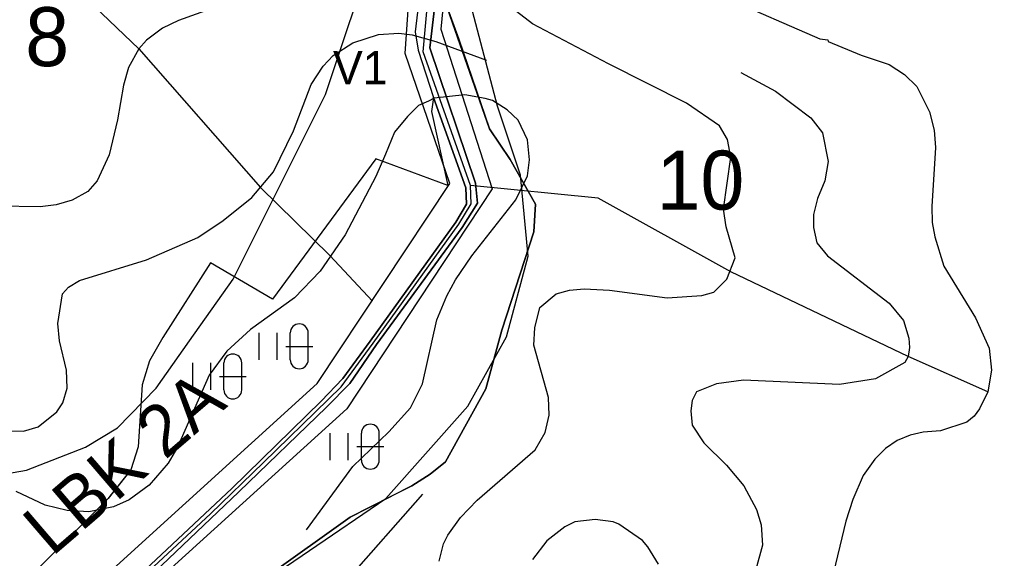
# Model space of a CAD drawing. Extents: x -662500 to -655523, y -1056000 to -1049993.
# Drawn here: x -660066.2 to -659685.9, y -1052866.9 to -1052656.8 of the extents above; entities that cross this region are included whole.
import ezdxf

# ---------------------------------------------------------------- set-up
doc = ezdxf.new("R2010")
doc.units = 0
for name, color, linetype in [('Vrstva 24', 7, 'Continuous'), ('Vrstva 32', 7, 'Continuous'), ('Vrstva 5', 7, 'Continuous'), ('Vrstva 51', 7, 'Continuous'), ('Vrstva 57', 7, 'Continuous'), ('Vrstva 7', 7, 'Continuous'), ('Vrstva 9', 7, 'Continuous')]:
    doc.layers.add(name, color=color, linetype=linetype)

msp = doc.modelspace()

# ---------------------------------------------------------------- linework, layer by layer
at = {"layer": 'Vrstva 24'}
for points in [[(-660034, -1052954), (-660032, -1052948.5), (-660000, -1052906.38), (-659983, -1052884), (-659923.5, -1052843.5), (-659891.5, -1052807.5), (-659876.5, -1052780.5), (-659868, -1052749), (-659871, -1052717.5), (-659880, -1052690.5), (-659893, -1052641), (-659893, -1052609.5), (-659864.5, -1052533), (-659861.5, -1052506), (-659866.5, -1052474.5), (-659880.5, -1052438.5), (-659901.5, -1052398), (-659927, -1052348.5), (-659940, -1052302)], [(-660132, -1052865), (-660131.5, -1052853), (-660124, -1052843), (-660063.5, -1052832.5), (-660040.5, -1052823.5), (-660028, -1052816), (-660013, -1052800.5), (-660000, -1052782.08), (-659983, -1052758), (-659947, -1052686), (-659927.5, -1052627.5), (-659920, -1052581), (-659923.5, -1052545), (-659933, -1052515), (-659946, -1052493), (-659958.5, -1052479), (-659977, -1052460), (-660000, -1052444.36), (-660002, -1052443), (-660058, -1052408.5), (-660084, -1052396), (-660097, -1052392.5), (-660103, -1052390), (-660138, -1052390)]]:
    msp.add_lwpolyline(points, dxfattribs=at)
at = {"layer": 'Vrstva 32'}
msp.add_lwpolyline([(-660043.52, -1052897.56), (-659991.83, -1052849.55), (-659971.21, -1052829.43), (-659940.88, -1052799.92), (-659928.36, -1052782.89), (-659895.08, -1052736.55), (-659890.22, -1052728.7), (-659890.47, -1052721.49), (-659908.9, -1052669.32), (-659905.49, -1052630.68), (-659904.41, -1052599.95), (-659898.52, -1052575.7), (-659893.12, -1052552.53), (-659895.67, -1052538.64), (-659900.78, -1052506.64), (-659903.72, -1052495.05), (-659933.15, -1052395.84), (-659942.2, -1052359.57), (-659946.03, -1052344.26)], dxfattribs=at)
at = {"layer": 'Vrstva 5'}
for points in [[(-659488.42, -1052589.49), (-659931.7, -1052394.49), (-659912.55, -1052459.34), (-659898.17, -1052506.06), (-659891.78, -1052526.8), (-659889.85, -1052537.24), (-659889.84, -1052553.2), (-659891.97, -1052560.5), (-659899.91, -1052591.56), (-659902.26, -1052610.6), (-659903.49, -1052643.35), (-659900.3, -1052649.88), (-659895.05, -1052664.49), (-659883.07, -1052699.38), (-659874.97, -1052711.4), (-659865.21, -1052728.83), (-659865.78, -1052739.54), (-659878.28, -1052777.87), (-659884.49, -1052800.77), (-659900.19, -1052829.18), (-659906.2, -1052834), (-659913.38, -1052838.57), (-659937.32, -1052850.73), (-659969.58, -1052873.81)], [(-659909.98, -1052643.89), (-659912.09, -1052661.63), (-659910.92, -1052668.79), (-659904.94, -1052687.24), (-659905.71, -1052692.7), (-659899.37, -1052721.44), (-659927.4, -1052711.06), (-659967.63, -1052765.86), (-659991.81, -1052751.6), (-660010.37, -1052780.75), (-660015.6, -1052789.79), (-660018.46, -1052799.22), (-660019.99, -1052823.38), (-660022.81, -1052832.29), (-660031.73, -1052843.45), (-660064, -1052875.84)], [(-659909.98, -1052643.89), (-659912.09, -1052661.63), (-659910.92, -1052668.79), (-659904.94, -1052687.24), (-659892.37, -1052722.42), (-659892.1, -1052728.71), (-659896.18, -1052735.72), (-659929.58, -1052782.17), (-659940.23, -1052796.79), (-659948.71, -1052805.54), (-659983.56, -1052839.55), (-660021.37, -1052875.26)], [(-659969.58, -1052873.81), (-659937.32, -1052850.73), (-659918.06, -1052840.85), (-659913.38, -1052838.57), (-659906.2, -1052834), (-659900.19, -1052829.18), (-659884.49, -1052800.77), (-659878.28, -1052777.87), (-659865.78, -1052739.54), (-659865.21, -1052728.83), (-659874.97, -1052711.4), (-659883.07, -1052699.38), (-659900.3, -1052649.88), (-659903.49, -1052643.35), (-659906.35, -1052667.8), (-659888.54, -1052720.54), (-659887.79, -1052728.34), (-659893.7, -1052737.91), (-659927.06, -1052783.51), (-659937.57, -1052798.73), (-659946.56, -1052807.92), (-659980.71, -1052840.86), (-660019.16, -1052877.46)], [(-660019.16, -1052877.46), (-659980.71, -1052840.86), (-659946.56, -1052807.92), (-659937.57, -1052798.73), (-659927.06, -1052783.51), (-659893.7, -1052737.91), (-659887.79, -1052728.34), (-659888.54, -1052720.54), (-659906.35, -1052667.8), (-659903.49, -1052643.35)], [(-660021.37, -1052875.26), (-659983.56, -1052839.55), (-659948.71, -1052805.54), (-659940.23, -1052796.79), (-659929.58, -1052782.17), (-659896.18, -1052735.72), (-659892.1, -1052728.71), (-659892.37, -1052722.42), (-659904.94, -1052687.24), (-659905.71, -1052692.7), (-659899.37, -1052721.44), (-659927.4, -1052711.06), (-659967.63, -1052765.86), (-659991.81, -1052751.6), (-660010.37, -1052780.75), (-660015.6, -1052789.79), (-660018.46, -1052799.22), (-660019.99, -1052823.38), (-660022.81, -1052832.29), (-660031.02, -1052842.56), (-660031.73, -1052843.45), (-660064, -1052875.84)], [(-659972.99, -1052778.94), (-659972.99, -1052789.44)], [(-659965.99, -1052778.94), (-659965.99, -1052789.44)], [(-659960.74, -1052789.44), (-659960.74, -1052778.94)], [(-659953.74, -1052789.44), (-659953.74, -1052778.94)], [(-659962.49, -1052784.19), (-659951.99, -1052784.19)]]:
    msp.add_lwpolyline(points, dxfattribs=at)
for centre, start, end in [((-659957.24, -1052778.94), 0, 180), ((-659957.24, -1052789.44), 180, 0)]:
    msp.add_arc(centre, 3.5, start, end, dxfattribs=at)
at = {"layer": 'Vrstva 51'}
for points in [[(-660169.13, -1053023.13), (-660110.85, -1052940.58), (-660079.74, -1052916.29), (-659950.2, -1052798.66), (-659898.58, -1052720.65), (-659915.89, -1052669.98), (-659910.89, -1052596.38), (-659900.42, -1052552.71), (-659942.19, -1052387.83), (-659921.6, -1052399.48), (-659893.5, -1052409.43), (-659785.78, -1052462.16), (-659600.37, -1052554.27), (-659621.1, -1052589.25), (-659403.17, -1052709.23)], [(-659408.68, -1052722.85), (-659645.22, -1052595.6), (-659623.64, -1052558.85), (-659899.32, -1052423.28), (-659921, -1052417.16), (-659884.97, -1052552.61), (-659896.01, -1052598.65), (-659902.05, -1052660.61), (-659882, -1052722.78), (-659938.73, -1052808.5), (-660070.07, -1052927.77), (-660099.87, -1052951.04), (-660151.35, -1053023.96)]]:
    msp.add_lwpolyline(points, dxfattribs=at)
at = {"layer": 'Vrstva 57'}
for points in [[(-660144.85, -1052500.62), (-660117.36, -1052556.07), (-660071.54, -1052618.58), (-660019.78, -1052668.15), (-659972.38, -1052722.21), (-659945.35, -1052748.76), (-659928.67, -1052766.62)], [(-659688.88, -1052801.93), (-659719.91, -1052788.18), (-659789.09, -1052755.11), (-659840.79, -1052726.44), (-659890.47, -1052721.49)]]:
    msp.add_lwpolyline(points, dxfattribs=at)
at = {"layer": 'Vrstva 7'}
for p, q in [((-659803.38, -1052642.92), (-659754.35, -1052664.32)), ((-659988.75, -1052651.56), (-660004.34, -1052657.23)), ((-659866.38, -1052658.42), (-659877.61, -1052649.73)), ((-660004.34, -1052657.23), (-660010.57, -1052660.21)), ((-660010.57, -1052660.21), (-660016.81, -1052664.89)), ((-659836.69, -1052674.1), (-659866.38, -1052658.42)), ((-659936.31, -1052665.88), (-659926.39, -1052662.62)), ((-659926.39, -1052662.62), (-659918.46, -1052662.05)), ((-659918.46, -1052662.05), (-659913.21, -1052662.76)), ((-659913.21, -1052662.76), (-659904, -1052665.31)), ((-659754.35, -1052664.32), (-659751.23, -1052664.75)), ((-659751.23, -1052664.75), (-659751.09, -1052665.31)), ((-660019.78, -1052668.15), (-660023.75, -1052675.52)), ((-660016.81, -1052664.89), (-660019.78, -1052668.15)), ((-659943.97, -1052670.84), (-659936.31, -1052665.88)), ((-659904, -1052665.31), (-659884.3, -1052672.68)), ((-659751.09, -1052665.31), (-659738.19, -1052670.7)), ((-659947.93, -1052674.95), (-659943.97, -1052670.84)), ((-659738.19, -1052670.7), (-659727.28, -1052674.38)), ((-660023.75, -1052675.52), (-660025.74, -1052682.32)), ((-659952.61, -1052682.18), (-659947.93, -1052674.95)), ((-659806.36, -1052689.4), (-659836.69, -1052674.1)), ((-659727.28, -1052674.38), (-659721.33, -1052678.21)), ((-659785.1, -1052677.5), (-659771.64, -1052684.73)), ((-659721.33, -1052678.21), (-659716.51, -1052682.89)), ((-660025.74, -1052682.32), (-660028, -1052695.92)), ((-659959.41, -1052700.17), (-659952.61, -1052682.18)), ((-659716.51, -1052682.89), (-659711.55, -1052692.8)), ((-659904.65, -1052687.39), (-659906.9, -1052688.56)), ((-659892.71, -1052686.16), (-659904.65, -1052687.39)), ((-659884.73, -1052687.56), (-659892.71, -1052686.16)), ((-659881.9, -1052688.41), (-659884.73, -1052687.56)), ((-659771.64, -1052684.73), (-659757.89, -1052695.07)), ((-659910.74, -1052690.26), (-659915.05, -1052694.56)), ((-659906.9, -1052688.56), (-659910.74, -1052690.26)), ((-659876.23, -1052691.95), (-659881.9, -1052688.41)), ((-659793.46, -1052698.19), (-659806.36, -1052689.4)), ((-659915.05, -1052694.56), (-659920.07, -1052700.67)), ((-659871.97, -1052696.06), (-659876.23, -1052691.95)), ((-659757.89, -1052695.07), (-659753.36, -1052701.02)), ((-659711.55, -1052692.8), (-659709.85, -1052699.89)), ((-660028, -1052695.92), (-660031.26, -1052709.53)), ((-659868.29, -1052703.72), (-659871.97, -1052696.06)), ((-659790.35, -1052703.57), (-659793.46, -1052698.19)), ((-659967.21, -1052716.19), (-659959.41, -1052700.17)), ((-659920.07, -1052700.67), (-659923.56, -1052709.24)), ((-659753.36, -1052701.02), (-659751.09, -1052712.08)), ((-659709.85, -1052699.89), (-659709.28, -1052706.69)), ((-659867.44, -1052711.51), (-659868.29, -1052703.72)), ((-659789.07, -1052710.38), (-659790.35, -1052703.57)), ((-659709.28, -1052706.69), (-659710.7, -1052729.65)), ((-660031.26, -1052709.53), (-660035.94, -1052719.73)), ((-659923.56, -1052709.24), (-659927.39, -1052718.03)), ((-659791.91, -1052730.78), (-659789.07, -1052710.38)), ((-659868.29, -1052717.75), (-659867.44, -1052711.51)), ((-659751.09, -1052712.08), (-659752.36, -1052719.73)), ((-659975.71, -1052726.11), (-659967.21, -1052716.19)), ((-659927.39, -1052718.03), (-659939.29, -1052740.71)), ((-659872.83, -1052727.1), (-659868.29, -1052717.75)), ((-660035.94, -1052719.73), (-660039.62, -1052723.84)), ((-659752.36, -1052719.73), (-659755.2, -1052726.53)), ((-660039.62, -1052723.84), (-660045.72, -1052727.24)), ((-660058.19, -1052729.79), (-660083.13, -1052729.51)), ((-660051.95, -1052729.08), (-660058.19, -1052729.79)), ((-660045.72, -1052727.24), (-660051.95, -1052729.08)), ((-659986.91, -1052735.18), (-659975.71, -1052726.11)), ((-659889.97, -1052748.93), (-659872.83, -1052727.1)), ((-659755.2, -1052726.53), (-659756.76, -1052732.77)), ((-659790.91, -1052737.59), (-659791.91, -1052730.78)), ((-659756.76, -1052732.77), (-659756.76, -1052737.87)), ((-659710.7, -1052729.65), (-659710.56, -1052735.89)), ((-659996.69, -1052741.7), (-659986.91, -1052735.18)), ((-659710.56, -1052735.89), (-659709.57, -1052741.55)), ((-659939.29, -1052740.71), (-659949.07, -1052754.88)), ((-659787.37, -1052749.63), (-659790.91, -1052737.59)), ((-659756.76, -1052737.87), (-659755.48, -1052743.82)), ((-660016.81, -1052750.48), (-659996.69, -1052741.7)), ((-659755.48, -1052743.82), (-659751.37, -1052748.92)), ((-659709.57, -1052741.55), (-659706.02, -1052752.89)), ((-660042.89, -1052758.56), (-660016.81, -1052750.48)), ((-659896.35, -1052758.28), (-659889.97, -1052748.93)), ((-659790.63, -1052758), (-659787.37, -1052749.63)), ((-659751.37, -1052748.92), (-659727.28, -1052767.35)), ((-659949.07, -1052754.88), (-659959.13, -1052765.22)), ((-659706.02, -1052752.89), (-659693.7, -1052773.02)), ((-660047.14, -1052761.11), (-660042.89, -1052758.56)), ((-659899.75, -1052764.51), (-659896.35, -1052758.28)), ((-659795.59, -1052763.1), (-659790.63, -1052758)), ((-660051.25, -1052775.28), (-660049.55, -1052763.66)), ((-660049.55, -1052763.66), (-660047.14, -1052761.11)), ((-659863.47, -1052769.05), (-659857.09, -1052763.66)), ((-659857.09, -1052763.66), (-659851.89, -1052762.32)), ((-659851.89, -1052762.32), (-659846.18, -1052761.82)), ((-659846.18, -1052761.82), (-659836.26, -1052762.25)), ((-659836.26, -1052762.25), (-659813.87, -1052765.22)), ((-659800.27, -1052764.37), (-659795.59, -1052763.1)), ((-659959.13, -1052765.22), (-659976.28, -1052777.69)), ((-659903.58, -1052773.87), (-659899.75, -1052764.51)), ((-659813.87, -1052765.22), (-659800.27, -1052764.37)), ((-659727.28, -1052767.35), (-659721.76, -1052774.15)), ((-659865.45, -1052776.99), (-659863.47, -1052769.05)), ((-659909.25, -1052798.81), (-659903.58, -1052773.87)), ((-659721.76, -1052774.15), (-659719.63, -1052780.95)), ((-659693.7, -1052773.02), (-659688.31, -1052784.92)), ((-660050.68, -1052782.09), (-660051.25, -1052775.28)), ((-659976.28, -1052777.69), (-659985.49, -1052786.05)), ((-659865.74, -1052783.79), (-659865.45, -1052776.99)), ((-660047.99, -1052793.42), (-660050.68, -1052782.09)), ((-659719.63, -1052780.95), (-659719.34, -1052784.64)), ((-659985.49, -1052786.05), (-659992.29, -1052795.41)), ((-659860.07, -1052804.19), (-659865.74, -1052783.79)), ((-659719.34, -1052784.64), (-659719.91, -1052788.18)), ((-659688.31, -1052784.92), (-659687.46, -1052793.42)), ((-659719.91, -1052788.18), (-659721.19, -1052790.45)), ((-660047.7, -1052800.51), (-660047.99, -1052793.42)), ((-659721.19, -1052790.45), (-659732.67, -1052796.82)), ((-659687.46, -1052793.42), (-659688.88, -1052801.93)), ((-659992.29, -1052795.41), (-660004.62, -1052823.47)), ((-659784.11, -1052797.39), (-659794.6, -1052798.81)), ((-659746.7, -1052799.09), (-659784.11, -1052797.39)), ((-659732.67, -1052796.82), (-659746.7, -1052799.09)), ((-660049.4, -1052806.18), (-660047.7, -1052800.51)), ((-659913.92, -1052808.16), (-659909.25, -1052798.81)), ((-659794.6, -1052798.81), (-659802.39, -1052801.93)), ((-659859.79, -1052811), (-659860.07, -1052804.19)), ((-659804.09, -1052805.33), (-659804.66, -1052809.3)), ((-659802.39, -1052801.93), (-659804.09, -1052805.33)), ((-659688.88, -1052801.93), (-659692.14, -1052808.59)), ((-660051.67, -1052809.72), (-660049.4, -1052806.18)), ((-659922.28, -1052817.52), (-659913.92, -1052808.16)), ((-659804.66, -1052809.3), (-659804.09, -1052814.96)), ((-659692.14, -1052808.59), (-659694.26, -1052811.42)), ((-660059.04, -1052815.53), (-660051.67, -1052809.72)), ((-659861.34, -1052817.8), (-659859.79, -1052811)), ((-659694.26, -1052811.42), (-659697.1, -1052813.69)), ((-660074.91, -1052816.95), (-660064.71, -1052817.23)), ((-660064.71, -1052817.23), (-660059.04, -1052815.53)), ((-659804.09, -1052814.96), (-659799.56, -1052821.77)), ((-659697.1, -1052813.69), (-659707.3, -1052817.09)), ((-659936.31, -1052830.98), (-659922.28, -1052817.52)), ((-659865.31, -1052824.6), (-659861.34, -1052817.8)), ((-659719.2, -1052818.79), (-659724.16, -1052820.92)), ((-659714.1, -1052817.66), (-659719.2, -1052818.79)), ((-659707.3, -1052817.09), (-659714.1, -1052817.66)), ((-660004.62, -1052823.47), (-660008.31, -1052829.7)), ((-659887.85, -1052844.16), (-659865.31, -1052824.6)), ((-659799.56, -1052821.77), (-659790.77, -1052830.55)), ((-659728.7, -1052824.03), (-659732.95, -1052828.14)), ((-659724.16, -1052820.92), (-659728.7, -1052824.03)), ((-659732.95, -1052828.14), (-659737.48, -1052834.52)), ((-660008.31, -1052829.7), (-660015.68, -1052838.35)), ((-659954.41, -1052855.78), (-659936.31, -1052830.98)), ((-659790.77, -1052830.55), (-659783.97, -1052838.63)), ((-659737.48, -1052834.52), (-659741.45, -1052843.88)), ((-660015.68, -1052838.35), (-660023.47, -1052844.02)), ((-659783.97, -1052838.63), (-659779.01, -1052847.84)), ((-660056.21, -1052846.14), (-660067.54, -1052840.76)), ((-659909.2, -1052841.78), (-659945.95, -1052883.55)), ((-660047.7, -1052848.13), (-660056.21, -1052846.14)), ((-660029.56, -1052846.71), (-660039.2, -1052848.69)), ((-660023.47, -1052844.02), (-660029.56, -1052846.71)), ((-659894.37, -1052850.96), (-659887.85, -1052844.16)), ((-659741.45, -1052843.88), (-659744.15, -1052852.38)), ((-660039.2, -1052848.69), (-660047.7, -1052848.13)), ((-659899.33, -1052857.76), (-659894.37, -1052850.96)), ((-659779.01, -1052847.84), (-659777.17, -1052853.79)), ((-659853.69, -1052854.5), (-659860.78, -1052860.03)), ((-659849.87, -1052852.66), (-659853.69, -1052854.5)), ((-659841.93, -1052851.67), (-659849.87, -1052852.66)), ((-659834.84, -1052852.66), (-659841.93, -1052851.67)), ((-659832.72, -1052853.51), (-659834.84, -1052852.66)), ((-659823.51, -1052859.89), (-659832.72, -1052853.51)), ((-659777.17, -1052853.79), (-659776.74, -1052861.73)), ((-659744.15, -1052852.38), (-659751.23, -1052881.29)), ((-659901.03, -1052861.16), (-659899.33, -1052857.76)), ((-659902.73, -1052867.97), (-659901.03, -1052861.16)), ((-659860.78, -1052860.03), (-659866.32, -1052867.24)), ((-659821.38, -1052862.3), (-659823.51, -1052859.89)), ((-659817.27, -1052869.1), (-659821.38, -1052862.3)), ((-659776.74, -1052861.73), (-659779.29, -1052871.23))]:
    msp.add_line(p, q, dxfattribs=at)
at = {"layer": 'Vrstva 9'}
for points in [[(-659998.87, -1052790.68), (-659998.87, -1052801.18)], [(-659991.87, -1052790.68), (-659991.87, -1052801.18)], [(-659986.62, -1052801.18), (-659986.62, -1052790.68)], [(-659979.62, -1052801.18), (-659979.62, -1052790.68)], [(-659988.37, -1052795.93), (-659977.87, -1052795.93)], [(-659945.28, -1052818.03), (-659945.28, -1052828.53)], [(-659938.28, -1052818.03), (-659938.28, -1052828.53)], [(-659933.03, -1052828.53), (-659933.03, -1052818.03)], [(-659926.03, -1052828.53), (-659926.03, -1052818.03)], [(-659934.78, -1052823.28), (-659924.28, -1052823.28)]]:
    msp.add_lwpolyline(points, dxfattribs=at)
for centre, start, end in [((-659983.12, -1052790.68), 0, 180), ((-659983.12, -1052801.18), 180, 0), ((-659929.53, -1052818.03), 0, 180), ((-659929.53, -1052828.53), 180, 0)]:
    msp.add_arc(centre, 3.5, start, end, dxfattribs=at)

# ---------------------------------------------------------------- texts
at = {"layer": 'Vrstva 32'}
msp.add_text('V1', height=13, rotation=360, dxfattribs=at).set_placement((-659944.08, -1052682.09))
at = {"layer": 'Vrstva 51'}
msp.add_text('LBK 2A', height=20, rotation=40.6166, dxfattribs=at).set_placement((-660053.59, -1052866.46))
at = {"layer": 'Vrstva 57'}
for s, p in [('8', (-660064.02, -1052674.98)), ('10', (-659817.99, -1052730.9))]:
    msp.add_text(s, height=23, dxfattribs=at).set_placement(p)

doc.saveas('drawing.dxf')
